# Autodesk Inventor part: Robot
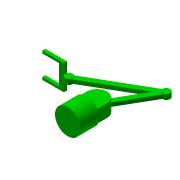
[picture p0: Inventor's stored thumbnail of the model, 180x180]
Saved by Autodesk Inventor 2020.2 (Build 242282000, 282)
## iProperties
Created: 2006-01
Part Number: Robot
Document SubType Name: Modeling
Designer: F.Stasiak
Density: 1 g/cm^3
Material: Ogólny
Appearance: Zielony
Manager: www.cadconsulting.pl
Company: Fabian Stasiak CAD Consulting
Author: F.Stasiak
Subject: Zbiór ćwiczeń. Autodesk Inventor 2020. Kurs podstawowy
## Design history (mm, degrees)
sketch "Szkic2"
  geometry: C1 r 500 at (0, 0) reference
  constraints: 1 centre point, 2 other
extrude "Wyciągnięcie proste1" new body sketch "Szkic2" distance "d0" = 750; taper "d1" = 0 deg
sketch "Szkic3"
  geometry: L1 (-500, 750)-(500, 750) reference; L2 (400, 750)-(400, 1150); L3 (-400, 1150)-(-400, 750); L4 (0, 750)-(0, 1150); L5 (-1424.871, 1482.051)-(1000, 2882.051); L6 (1000, 2882.051)-(0, 1150); L7 (1030.701, 2735.226)-(280.252, 1435.41); L8 (857.496, 2835.226)-(107.047, 1535.41); L9 (-1378.047, 1624.555)-(853.175, 2912.752); L10 (-1278.047, 1451.35)-(726.795, 2608.846); L11 (-1562.348, 1542.051)-(-2424.871, 1542.051); L12 (-1562.348, 1422.051)-(-2424.871, 1422.051); L13 (-2424.871, 1542.051)-(-2424.871, 1422.051); L14 (-1424.871, 1482.051)-(-2424.871, 1482.051); A1 r 400 centre (0, 1150) between (400, 1150) and (-400, 1150); A2 r 150 centre (1000, 2882.051) between (857.496, 2835.226) and (1030.701, 2735.226); A3 r 150 centre (-1424.871, 1482.051) between (-1278.047, 1451.35) and (-1378.047, 1624.555)
  constraints: 26 end point, 11 point on circle, 6 parallel, 3 centre point, 3 perpendicular, 3 point on line, 2 midpoint, 2 tangent, 1 coincident, 1 equal radius, 1 horizontal
  dimensions: "d2" = 400 distance from line of L1 L4.end; "d3" = 400 radius of A1; "d4" = 100 distance between parallel lines of L6 L7; "d5" = 100 distance between parallel lines of L8 L6; "d6" = 100 distance between parallel lines of L9 L5; "d8" = 300 diameter of A2; "d12" = 150 deg angle of L4 L6; "d13" = 30 deg angle of L5 L6; "d14" = 2800 distance of L5.start L5.end; "d15" = 2000 distance of L5.end L4.end; "d16" = 100 distance between parallel lines of L5 L10 (= d6); "d31" = 120 distance of L11.end L12.end; "d32" = 1000 distance from line of L14.start L13
extrude "Wyciągnięcie proste2" join sketch "Szkic3" stored distance "d18" = 500; taper "d19" = 0 deg
extrude "Wyciągnięcie proste3" join sketch "Szkic3" stored distance "d20" = 200; taper "d21" = 0 deg
extrude "Wyciągnięcie proste4" join sketch "Szkic3" stored distance "d22" = 150; taper "d23" = 0 deg
extrude "Wyciągnięcie proste5" join sketch "Szkic3" stored distance "d24" = 1000; taper "d25" = 0 deg
sketch "Szkic4"
  geometry: L1 (0, 1000)-(0, 0) reference; L2 (0, 900)-(662.523, 900); L3 (662.523, 900)-(662.523, 100); L4 (662.523, 100)-(0, 100); L5 (862.523, 0)-(0, 0) reference; L6 (862.523, 1000)-(0, 1000) reference; L7 (862.523, 600)-(862.523, 1000) reference
  constraints: 6 end point, 2 perpendicular, 2 point on line, 1 parallel
  dimensions: "d26" = 100 distance between parallel lines of L5 L4; "d27" = 100 distance between parallel lines of L6 L2 (= d26); "d28" = 200 distance between parallel lines of L7 L3
extrude "Wyciągnięcie proste6" cut sketch "Szkic4" extent not by distance; stored distance "d29" = 1000; taper "d30" = 0 deg
node "Bryła1"
node "Korpusy bryłowe"
node "Korpusy powierzchniowe"
